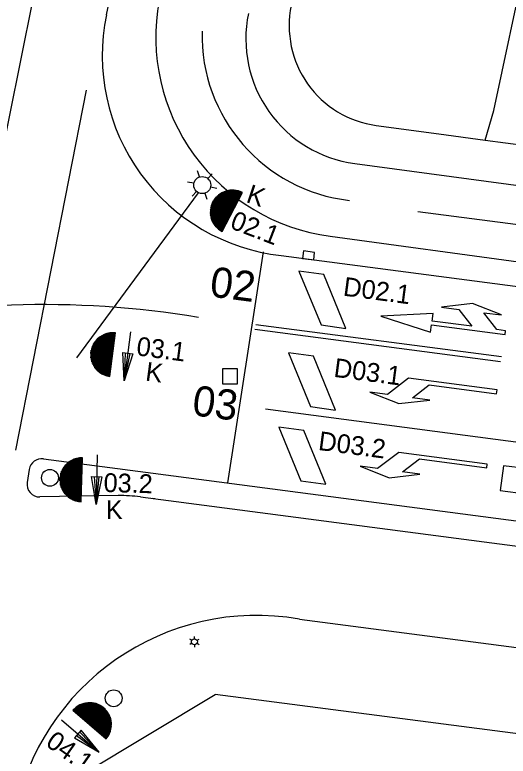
# Model space of a CAD drawing. Extents: x 81065 to 81486, y 452384 to 452681.
# Drawn here: x 81233.14 to 81252.76, y 452511.24 to 452540.73 of the extents above; entities that cross this region are included whole.
import ezdxf

# ---------------------------------------------------------------- set-up
doc = ezdxf.new("R2010")
doc.units = 0
for name, color, linetype in [('B-BH-GR-GROENVOORZIENING-GV', 7, 'Continuous'), ('B-BH-IE-MEUBILAIR_WEGMEUBILAIR_LICHTMAST-S', 7, 'Continuous'), ('B-BH-RI-GWA_RIOOLPUT-S', 7, 'Continuous'), ('B-BH-VH-KANTOPSLUITING-GV', 7, 'Continuous'), ('B-SRI-KOLK_COMBINATIE-S', 7, 'Continuous'), ('B-WE-VW-MARKERING_DWARS_DRIEHOEK_5050-G', 7, 'Continuous'), ('B-WE-VW-MARKERING_DWARS_STOPSTREEP_030-G', 7, 'Continuous'), ('B-WE-VW-MARKERING_LANGS_STREEP_11_010-G', 7, 'Continuous'), ('B-WE-VW-MARKERING_LANGS_STREEP_13_010-G', 7, 'Continuous'), ('B-WE-VW-MARKERING_LANGS_STREEP_30270_010-G', 7, 'Continuous'), ('B-WE-VW-MARKERING_LANGS_STREEP_DOORGETROKKEN_010-G', 7, 'Continuous'), ('B-WE-VW-MARKERING_PIJL-S', 7, 'Continuous'), ('N-OI-KL-VRI_LUS_DETECTIE-G', 7, 'Continuous'), ('N-OI-KL-VRI_LUS_DETECTIE-T18', 7, 'Continuous'), ('N-WE-VW-VRI_ARMATUUR-S', 7, 'Continuous'), ('N-WE-VW-VRI_ARMATUUR-T18', 7, 'Continuous'), ('N-WE-VW-VRI_LIGGER-G', 7, 'Continuous'), ('N-WE-VW-VRI_MAST-S', 7, 'Continuous'), ('N-WE-VW-VRI_RICHTINGNUMMER-T25', 7, 'Continuous')]:
    doc.layers.add(name, color=color, linetype=linetype)

msp = doc.modelspace()

# ---------------------------------------------------------------- linework, layer by layer
at = {"layer": 'B-BH-GR-GROENVOORZIENING-GV'}
msp.add_lwpolyline([(81251.835, 452535.75), (81252.192, 452536.931), (81257.329, 452561.023), (81263.916, 452591.926), (81268.85, 452615.069)], dxfattribs=at)
at = {"layer": 'B-BH-IE-MEUBILAIR_WEGMEUBILAIR_LICHTMAST-S'}
for p, q in [((81240.176, 452515.849), (81240.098, 452515.894)), ((81240.28, 452515.909), (81240.28, 452515.999)), ((81240.384, 452515.849), (81240.462, 452515.894)), ((81240.176, 452515.729), (81240.098, 452515.684)), ((81240.28, 452515.669), (81240.28, 452515.579)), ((81240.384, 452515.729), (81240.462, 452515.684))]:
    msp.add_line(p, q, dxfattribs=at)
msp.add_circle((81240.28, 452515.789), 0.12, dxfattribs=at)
at = {"layer": 'B-BH-RI-GWA_RIOOLPUT-S'}
for p, q in [((81241.997, 452526.655), (81241.39, 452526.655)), ((81241.39, 452526.655), (81241.39, 452526.048)), ((81241.997, 452526.048), (81241.997, 452526.655)), ((81241.39, 452526.048), (81241.997, 452526.048))]:
    msp.add_line(p, q, dxfattribs=at)
at = {"layer": 'B-BH-VH-KANTOPSLUITING-GV'}
for p, q in [((81236.779, 452540.734), (81237.258, 452543.046)), ((81247.512, 452536.333), (81250, 452535.998)), ((81250, 452535.998), (81251.835, 452535.75)), ((81251.835, 452535.75), (81257.241, 452535.02)), ((81246.656, 452534.817), (81276.688, 452530.764)), ((81245.674, 452531.923), (81278.234, 452527.528)), ((81233.713, 452522.651), (81233.631, 452522.131)), ((81235.82, 452510.52), (81241.105, 452513.698))]:
    msp.add_line(p, q, dxfattribs=at)
for points in [[(81243.726, 452531.159), (81265.878, 452528.256), (81277.986, 452526.694)], [(81234.272, 452523.069), (81238.637, 452522.497)], [(81238.637, 452522.497), (81260.64, 452519.613)], [(81237.252, 452521.605), (81234.133, 452521.553)], [(81238.131, 452521.555), (81260.51, 452518.622)], [(81238.7, 452521.48), (81238.606, 452521.493)], [(81244.457, 452516.692), (81259.99, 452514.656)], [(81264.058, 452510.715), (81241.105, 452513.698)]]:
    msp.add_lwpolyline(points, dxfattribs=at)
for centre, radius, start, end in [((81246.744, 452539.851), 8, 169.6049, 262.3134), ((81248.046, 452540.297), 4, 168.3092, 262.3382), ((81244.613, 452539.111), 8, 168.2954, 263.6346), ((81247.324, 452539.772), 5, 168.3092, 262.3134), ((81234.207, 452522.573), 0.5, 82.5333, 171.0319), ((81234.125, 452522.053), 0.5, 171.0319, 270.9555), ((81237.352, 452515.606), 6, 82.5333, 90.9555), ((81242.762, 452507.028), 9.811, 80.0525, 169.5766)]:
    msp.add_arc(centre, radius, start, end, dxfattribs=at)
at = {"layer": 'B-SRI-KOLK_COMBINATIE-S'}
for p, q in [((81244.616, 452531.338), (81244.578, 452531.046)), ((81245.06, 452531.28), (81244.616, 452531.338)), ((81245.022, 452530.987), (81245.06, 452531.28)), ((81244.578, 452531.046), (81245.022, 452530.987))]:
    msp.add_line(p, q, dxfattribs=at)
at = {"layer": 'B-WE-VW-MARKERING_DWARS_DRIEHOEK_5050-G'}
msp.add_lwpolyline([(81233.172, 452523.418), (81235.993, 452537.74)], dxfattribs=at)
at = {"layer": 'B-WE-VW-MARKERING_DWARS_STOPSTREEP_030-G'}
msp.add_line((81243.015, 452531.307), (81241.593, 452522.119), dxfattribs=at)
at = {"layer": 'B-WE-VW-MARKERING_LANGS_STREEP_11_010-G'}
msp.add_arc((81234.269, 452491.876), 37.331, 80.4782, 103.4068, dxfattribs=at)
at = {"layer": 'B-WE-VW-MARKERING_LANGS_STREEP_13_010-G'}
for p, q in [((81233.846, 452541.285), (81227.841, 452511.692)), ((81243.1, 452525.055), (81268.889, 452521.675))]:
    msp.add_line(p, q, dxfattribs=at)
at = {"layer": 'B-WE-VW-MARKERING_LANGS_STREEP_30270_010-G'}
msp.add_line((81249.168, 452532.914), (81278.225, 452529.119), dxfattribs=at)
msp.add_arc((81247.197, 452539.924), 6.617, 178.6099, 263.4439, dxfattribs=at)
at = {"layer": 'B-WE-VW-MARKERING_LANGS_STREEP_DOORGETROKKEN_010-G'}
for p, q in [((81252.492, 452527.121), (81242.725, 452528.401)), ((81252.445, 452526.932), (81242.678, 452528.212))]:
    msp.add_line(p, q, dxfattribs=at)
at = {"layer": 'B-WE-VW-MARKERING_PIJL-S'}
for p, q in [((81251.334, 452529.247), (81250.106, 452529.105)), ((81252.485, 452528.794), (81251.334, 452529.247)), ((81249.769, 452528.847), (81247.688, 452528.742)), ((81249.73, 452528.549), (81249.769, 452528.847)), ((81250.106, 452529.105), (81250.8, 452529.014)), ((81250.8, 452529.014), (81251.317, 452528.342)), ((81252.308, 452528.212), (81251.791, 452528.884)), ((81251.791, 452528.884), (81252.485, 452528.794)), ((81247.688, 452528.742), (81249.672, 452528.103)), ((81251.317, 452528.342), (81249.73, 452528.549)), ((81249.672, 452528.103), (81249.711, 452528.401)), ((81249.711, 452528.401), (81252.636, 452528.017)), ((81252.655, 452528.166), (81252.308, 452528.212)), ((81252.636, 452528.017), (81252.655, 452528.166)), ((81248.796, 452526.277), (81247.954, 452525.633)), ((81252.315, 452525.808), (81248.796, 452526.277)), ((81248.945, 452525.501), (81249.619, 452526.016)), ((81249.619, 452526.016), (81252.295, 452525.66)), ((81247.954, 452525.633), (81247.26, 452525.725)), ((81247.26, 452525.725), (81248.41, 452525.269)), ((81252.295, 452525.66), (81252.315, 452525.808)), ((81248.41, 452525.269), (81249.639, 452525.408)), ((81249.639, 452525.408), (81248.945, 452525.501)), ((81248.405, 452523.326), (81247.563, 452522.682)), ((81251.924, 452522.857), (81248.405, 452523.326)), ((81248.554, 452522.55), (81249.228, 452523.065)), ((81249.228, 452523.065), (81251.904, 452522.709)), ((81247.563, 452522.682), (81246.869, 452522.774)), ((81246.869, 452522.774), (81248.019, 452522.318)), ((81251.904, 452522.709), (81251.924, 452522.857)), ((81248.019, 452522.318), (81249.248, 452522.457)), ((81249.248, 452522.457), (81248.554, 452522.55))]:
    msp.add_line(p, q, dxfattribs=at)
at = {"layer": 'N-OI-KL-VRI_LUS_DETECTIE-G'}
for p, q in [((81244.436, 452530.53), (81245.313, 452528.394)), ((81245.427, 452530.397), (81244.436, 452530.53)), ((81246.303, 452528.26), (81245.427, 452530.397)), ((81245.313, 452528.394), (81246.303, 452528.26)), ((81244.022, 452527.281), (81244.899, 452525.145)), ((81245.013, 452527.148), (81244.022, 452527.281)), ((81245.889, 452525.011), (81245.013, 452527.148)), ((81244.899, 452525.145), (81245.889, 452525.011)), ((81243.636, 452524.333), (81244.513, 452522.197)), ((81244.627, 452524.2), (81243.636, 452524.333)), ((81243.636, 452524.333), (81244.513, 452522.197)), ((81244.627, 452524.2), (81243.636, 452524.333)), ((81245.503, 452522.064), (81244.627, 452524.2)), ((81245.503, 452522.064), (81244.627, 452524.2)), ((81252.571, 452522.794), (81252.441, 452521.804)), ((81272.4, 452520.193), (81252.571, 452522.794)), ((81244.513, 452522.197), (81245.503, 452522.064)), ((81244.513, 452522.197), (81245.503, 452522.064)), ((81252.441, 452521.804), (81272.271, 452519.201))]:
    msp.add_line(p, q, dxfattribs=at)
at = {"layer": 'N-WE-VW-VRI_ARMATUUR-S'}
for p, q in [((81240.912, 452532.844), (81241.328, 452533.633)), ((81240.913, 452532.904), (81241.276, 452533.598)), ((81240.918, 452532.786), (81241.378, 452533.661)), ((81240.924, 452532.737), (81241.421, 452533.682)), ((81240.935, 452532.689), (81241.467, 452533.701)), ((81240.947, 452532.647), (81241.508, 452533.718)), ((81240.959, 452532.606), (81241.55, 452533.729)), ((81240.973, 452532.568), (81241.589, 452533.739)), ((81240.988, 452532.533), (81241.627, 452533.747)), ((81241.004, 452532.498), (81241.664, 452533.753)), ((81241.021, 452532.466), (81241.701, 452533.758)), ((81241.039, 452532.435), (81241.736, 452533.761)), ((81241.057, 452532.406), (81241.77, 452533.76)), ((81241.078, 452532.378), (81241.804, 452533.761)), ((81241.096, 452532.351), (81241.839, 452533.76)), ((81241.117, 452532.326), (81241.87, 452533.757)), ((81241.136, 452532.302), (81241.9, 452533.755)), ((81241.16, 452532.279), (81241.931, 452533.749)), ((81241.181, 452532.258), (81241.964, 452533.743)), ((81241.205, 452532.236), (81241.992, 452533.737)), ((81241.229, 452532.216), (81242.022, 452533.729)), ((81241.251, 452532.198), (81242.053, 452533.719)), ((81241.277, 452532.179), (81242.08, 452533.711)), ((81241.302, 452532.162), (81242.108, 452533.699)), ((81241.327, 452532.144), (81242.136, 452533.688)), ((81241.353, 452532.13), (81242.165, 452533.674)), ((81241.379, 452532.115), (81242.192, 452533.661)), ((81240.917, 452532.977), (81241.217, 452533.552)), ((81240.932, 452533.07), (81241.15, 452533.489)), ((81240.986, 452533.237), (81241.044, 452533.352)), ((81236.403, 452526.601), (81236.583, 452527.962)), ((81236.431, 452526.575), (81236.616, 452527.98)), ((81236.458, 452526.55), (81236.648, 452527.997)), ((81236.486, 452526.529), (81236.68, 452528.013)), ((81236.513, 452526.507), (81236.712, 452528.024)), ((81236.541, 452526.488), (81236.744, 452528.036)), ((81236.569, 452526.469), (81236.776, 452528.047)), ((81236.597, 452526.452), (81236.807, 452528.055)), ((81236.626, 452526.436), (81236.836, 452528.06)), ((81236.652, 452526.423), (81236.867, 452528.07)), ((81236.68, 452526.41), (81236.9, 452528.075)), ((81236.711, 452526.397), (81236.929, 452528.078)), ((81236.738, 452526.388), (81236.96, 452528.082)), ((81236.767, 452526.378), (81236.992, 452528.084)), ((81236.798, 452526.37), (81237.021, 452528.084)), ((81236.827, 452526.363), (81237.051, 452528.086)), ((81236.857, 452526.356), (81237.081, 452528.083)), ((81236.886, 452526.35), (81237.111, 452528.081)), ((81236.916, 452526.345), (81237.143, 452528.08)), ((81237.74, 452528.128), (81237.484, 452526.174)), ((81236.205, 452526.924), (81236.305, 452527.7)), ((81236.229, 452526.868), (81236.343, 452527.75)), ((81236.251, 452526.815), (81236.38, 452527.795)), ((81236.274, 452526.771), (81236.413, 452527.831)), ((81236.3, 452526.73), (81236.449, 452527.863)), ((81236.326, 452526.695), (81236.481, 452527.894)), ((81236.352, 452526.661), (81236.517, 452527.92)), ((81236.378, 452526.629), (81236.55, 452527.94)), ((81236.156, 452527.262), (81236.173, 452527.39)), ((81236.166, 452527.086), (81236.225, 452527.555)), ((81236.184, 452526.995), (81236.266, 452527.639)), ((81237.484, 452526.174), (81237.429, 452527.296)), ((81237.429, 452527.296), (81237.828, 452527.246)), ((81237.527, 452527.283), (81237.484, 452526.174)), ((81237.714, 452527.26), (81237.484, 452526.174)), ((81237.828, 452527.246), (81237.484, 452526.174)), ((81235.276, 452521.544), (81235.31, 452522.96)), ((81235.306, 452521.522), (81235.341, 452522.98)), ((81235.335, 452521.503), (81235.371, 452523)), ((81235.365, 452521.484), (81235.402, 452523.014)), ((81235.395, 452521.469), (81235.432, 452523.029)), ((81235.424, 452521.453), (81235.462, 452523.044)), ((81235.454, 452521.438), (81235.493, 452523.055)), ((81235.485, 452521.426), (81235.521, 452523.063)), ((81235.511, 452521.416), (81235.551, 452523.076)), ((81235.541, 452521.406), (81235.583, 452523.085)), ((81235.573, 452521.396), (81235.612, 452523.091)), ((81235.601, 452521.39), (81235.642, 452523.098)), ((81235.631, 452521.383), (81235.674, 452523.103)), ((81235.662, 452521.378), (81235.702, 452523.107)), ((81235.692, 452521.375), (81235.732, 452523.111)), ((81235.722, 452521.371), (81235.762, 452523.111)), ((81235.752, 452521.368), (81235.792, 452523.113)), ((81235.782, 452521.366), (81235.824, 452523.115)), ((81236.413, 452523.227), (81236.366, 452521.256)), ((81235.044, 452521.813), (81235.064, 452522.702)), ((81235.072, 452521.763), (81235.095, 452522.751)), ((81235.099, 452521.722), (81235.124, 452522.791)), ((81235.13, 452521.683), (81235.157, 452522.826)), ((81235.159, 452521.651), (81235.186, 452522.86)), ((81235.188, 452521.621), (81235.219, 452522.889)), ((81235.217, 452521.591), (81235.249, 452522.914)), ((81235.245, 452521.566), (81235.28, 452522.939)), ((81234.958, 452522.023), (81234.967, 452522.496)), ((81234.986, 452521.935), (81234.999, 452522.584)), ((81235.014, 452521.866), (81235.031, 452522.649)), ((81236.366, 452521.256), (81236.191, 452522.366)), ((81236.191, 452522.366), (81236.593, 452522.359)), ((81236.29, 452522.363), (81236.366, 452521.256)), ((81236.479, 452522.361), (81236.366, 452521.256)), ((81236.593, 452522.359), (81236.366, 452521.256)), ((81234.93, 452522.197), (81234.933, 452522.326)), ((81235.629, 452513.227), (81236.903, 452512.135)), ((81235.655, 452513.244), (81236.916, 452512.163)), ((81235.68, 452513.258), (81236.925, 452512.195)), ((81235.71, 452513.275), (81236.937, 452512.223)), ((81235.739, 452513.289), (81236.948, 452512.253)), ((81235.77, 452513.302), (81236.957, 452512.286)), ((81235.801, 452513.315), (81236.964, 452512.318)), ((81235.834, 452513.326), (81236.971, 452512.352)), ((81235.868, 452513.338), (81236.976, 452512.387)), ((81235.903, 452513.347), (81236.98, 452512.423)), ((81235.94, 452513.355), (81236.981, 452512.461)), ((81235.978, 452513.362), (81236.982, 452512.5)), ((81236.018, 452513.366), (81236.982, 452512.541)), ((81236.061, 452513.369), (81236.979, 452512.583)), ((81236.105, 452513.372), (81236.973, 452512.628)), ((81236.153, 452513.371), (81236.965, 452512.674)), ((81236.203, 452513.366), (81236.953, 452512.723)), ((81236.258, 452513.355), (81236.936, 452512.778)), ((81236.32, 452513.346), (81236.914, 452512.836)), ((81236.39, 452513.325), (81236.884, 452512.902)), ((81236.477, 452513.29), (81236.836, 452512.983)), ((81235.446, 452513.067), (81236.774, 452511.929)), ((81235.467, 452513.088), (81236.791, 452511.954)), ((81235.487, 452513.11), (81236.81, 452511.977)), ((81235.509, 452513.131), (81236.828, 452512.001)), ((81235.53, 452513.152), (81236.845, 452512.027)), ((81235.554, 452513.172), (81236.86, 452512.053)), ((81235.579, 452513.191), (81236.875, 452512.079)), ((81235.603, 452513.21), (81236.89, 452512.107)), ((81236.627, 452513.201), (81236.725, 452513.117)), ((81234.99, 452512.684), (81236.487, 452511.401)), ((81235.777, 452512.274), (81235.513, 452511.971)), ((81235.589, 452512.056), (81236.487, 452511.401)), ((81235.714, 452512.201), (81236.487, 452511.401)), ((81236.487, 452511.401), (81235.777, 452512.274)), ((81235.513, 452511.971), (81236.487, 452511.401))]:
    msp.add_line(p, q, dxfattribs=at)
for centre, start, end in [((81241.785, 452532.888), 62.2535, 242.2535), ((81237.03, 452527.211), 82.5333, 262.5333), ((81235.804, 452522.239), 88.6249, 268.6249), ((81236.108, 452512.497), 319.4035, 139.4035)]:
    msp.add_arc(centre, 0.873, start, end, dxfattribs=at)
at = {"layer": 'N-WE-VW-VRI_LIGGER-G'}
msp.add_line((81240.43, 452533.658), (81235.591, 452527.09), dxfattribs=at)
at = {"layer": 'N-WE-VW-VRI_MAST-S'}
for p, q in [((81240.484, 452534.285), (81240.404, 452534.527)), ((81240.817, 452534.216), (81240.987, 452534.407)), ((81240.259, 452534.031), (81240.009, 452534.082)), ((81240.924, 452533.893), (81241.174, 452533.842)), ((81240.366, 452533.708), (81240.196, 452533.517)), ((81240.699, 452533.639), (81240.779, 452533.397))]:
    msp.add_line(p, q, dxfattribs=at)
for centre, radius in [((81240.591, 452533.962), 0.34), ((81234.535, 452522.314), 0.335), ((81237.068, 452513.542), 0.335)]:
    msp.add_circle(centre, radius, dxfattribs=at)

# ---------------------------------------------------------------- texts
at = {"layer": 'N-OI-KL-VRI_LUS_DETECTIE-T18'}
for s, p in [('D02.1', (81246.167, 452529.565)), ('D03.1', (81245.793, 452526.336)), ('D03.2', (81245.177, 452523.426))]:
    msp.add_text(s, height=0.75, rotation=352.5333, dxfattribs=at).set_placement(p)
at = {"layer": 'N-WE-VW-VRI_ARMATUUR-S'}
for rotation, p in [(341.4361, (81242.297, 452533.293)), (352.4515, (81238.303, 452526.186)), (0.375, (81236.759, 452520.67))]:
    msp.add_text('K', height=0.75, rotation=rotation, dxfattribs=at).set_placement(p)
at = {"layer": 'N-WE-VW-VRI_ARMATUUR-T18'}
for s, rotation, p in [('02.1', 338.8675, (81241.655, 452532.258)), ('03.1', 352.5333, (81237.944, 452527.191)), ('03.2', 358.3923, (81236.66, 452521.752)), ('04.1', 324.7531, (81234.32, 452511.682))]:
    msp.add_text(s, height=0.75, rotation=rotation, dxfattribs=at).set_placement(p)
at = {"layer": 'N-WE-VW-VRI_RICHTINGNUMMER-T25'}
for s, p in [('02', (81240.852, 452529.536)), ('03', (81240.151, 452524.813))]:
    msp.add_text(s, height=1.2, rotation=352.5333, dxfattribs=at).set_placement(p)

doc.saveas('drawing.dxf')
